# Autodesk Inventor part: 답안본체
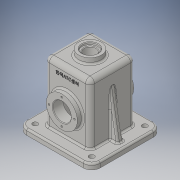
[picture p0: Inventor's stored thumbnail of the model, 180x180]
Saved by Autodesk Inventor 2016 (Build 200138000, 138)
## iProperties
Created: 2022-11
Part Number: 답안본체
Material: 일반
Document SubType Name: Modeling
Designer: CAD-13
Density: 1 g/cm^3
Appearance: 기본값
Author: CAD-13
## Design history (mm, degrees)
sketch "스케치1"
  geometry: L1 (40, -40)-(-40, -40); L2 (-40, -40)-(-40, 40); L3 (-40, 40)-(40, 40); L4 (40, 40)-(40, -40); L5 (40, -40)-(-40, 40); L6 (-40, -40)-(40, 40); 1 further point
  constraints: 12 end point, 2 midpoint, 2 parallel, 1 horizontal, 1 perpendicular
  dimensions: "d0" = 80 distance of L2.end L3.end; "d1" = 80 distance of L1.end L2.end
extrude "돌출1" new body sketch "스케치1" distance "d2" = 117; taper "d3" = 0 deg
feature "쉘1" dims "d4" = 8
node "작업 평면1"
sketch "스케치3"
  geometry: L1 (65, -62)-(-65, -62); L2 (-65, -62)-(-65, 62); L3 (-65, 62)-(65, 62); L4 (65, 62)-(65, -62); L5 (65, -62)-(-65, 62); L6 (-65, -62)-(65, 62); 1 further point
  constraints: 12 end point, 2 midpoint, 2 parallel, 1 horizontal, 1 perpendicular
  dimensions: "d6" = 130 distance of L2.end L3.end; "d7" = 124 distance of L1.end L2.end
extrude "돌출2" join sketch "스케치3" distance "d8" = 10; taper "d9" = 0 deg
sketch "스케치4"
  geometry: L1 (105, -117)-(-25, -117) reference; L2 (0, 0)-(80, 0) reference; C1 r 27.5 at (40, -62); 2 further points
  constraints: 1 centre point, 1 midpoint, 1 vertical alignment
  dimensions: "d10" = 55 diameter of C1; "d11" = 55 distance from line of L1 C1.centre
extrude "돌출3" join sketch "스케치4" distance "d12" = 10; taper "d13" = 0 deg
sketch "스케치5"
  geometry: C1 r 16 at (0, 0); 1 further point
  constraints: 1 centre point
  dimensions: "d14" = 32 diameter of C1
extrude "돌출4" cut sketch "스케치5" stored distance "d15" = 10; taper "d16" = 0 deg
sketch "스케치6"
  geometry: C1 r 20 at (0, 0); 1 further point
  constraints: 1 centre point, 1 coincident
  dimensions: "d17" = 40 diameter of C1
extrude "돌출5" join sketch "스케치6" distance "d18" = 10; taper "d19" = 0 deg
node "작업 평면2"
sketch "스케치7"
  geometry: L1 (40, 10)-(40, 117); L2 (40, 91.279)-(54.332, 10); L3 (-62, 10)-(64.332, 10); L4 (40, 10)-(40, 91.279); L5 (40, 10)-(54.332, 10); 1 further point
  constraints: 10 end point, 2 point on line
  dimensions: "d21" = 10 distance of L2.end L3.end; "d22" = 100 deg angle of L3 L2
extrude "돌출6" join sketch "스케치7" stored distance "d23" = 10; taper "d24" = 0 deg
sketch "스케치8"
  geometry: C1 r 14 at (0, 0); 1 further point
  constraints: 1 centre point, 1 coincident
  dimensions: "d25" = 28 diameter of C1
extrude "돌출7" cut sketch "스케치8" distance "d26" = 4; taper "d27" = 0 deg
sketch "스케치9"
  geometry: C1 r 10.5 at (0, 0); 1 further point
  constraints: 1 centre point, 1 coincident
  dimensions: "d28" = 21 diameter of C1
extrude "돌출8" cut sketch "스케치9" stored distance "d29" = 4; taper "d30" = 0 deg
fillet "모깎기1" dims "d31" = 8
fillet "모깎기2" dims "d32" = 8
fillet "모깎기3" dims "d33" = 15
fillet "모깎기4" dims "d34" = 3
sketch "스케치10"
  geometry: C1 r 4.5 at (-50, 47); C2 r 4.5 at (50, 47); C3 r 4.5 at (50, -47); C4 r 4.5 at (-50, -47); A1 r 15 centre (-50, 47) between (-50, 62) and (-65, 47) reference; A2 r 12 centre (50, 47) between (62, 47) and (50, 59) reference; A3 r 12 centre (50, -47) between (50, -59) and (62, -47) reference; A4 r 15 centre (-50, -47) between (-65, -47) and (-50, -62) reference; 1 further point
  constraints: 4 centre point, 4 coincident
  dimensions: "d35" = 9 diameter of C1; "d36" = 9 diameter of C2; "d37" = 9 diameter of C3; "d38" = 9 diameter of C4
extrude "돌출9" cut sketch "스케치10" stored distance "d39" = 0; taper "d40" = 0 deg
sketch "스케치11" dims "d41" = 45
  geometry: 3 further points
  constraints: 2 vertical alignment, 2 other
hole "구멍1" sketch "스케치11" at (0, 22.5) diameter "d42" = 3.242; stored, may be unused: countersink angle "d46" = 90 deg, drill point angle "d48" = 118 deg; dims "d43" = 8, "d44" = 4, "d45" = 2, "d47" = 10
fillet "모깎기5" dims "d52" = 3
fillet "모깎기6" dims "d53" = 3
chamfer "모따기1" distance "d54" = 1; stored, may be unused: second distance "d55" = 2, angle "d56" = 45 deg
chamfer "모따기2" distance "d57" = 1; stored, may be unused: second distance "d58" = 2, angle "d59" = 45 deg
fillet "모깎기7" dims "d60" = 3
fillet "모깎기8" dims "d61" = 3
sketch "스케치12"
  geometry: L1 (-32, -32)-(32, -32); L2 (32, -32)-(32, 32); L3 (32, 32)-(-32, 32); L4 (-32, 32)-(-32, -32); L5 (-32, -32)-(32, 32); L6 (32, -32)-(-32, 32); 1 further point
  constraints: 12 end point, 2 midpoint, 2 parallel, 1 horizontal, 1 perpendicular
  dimensions: "d62" = 64 distance of L3.end L2.end; "d63" = 64 distance of L2.end L1.end
extrude "돌출10" cut sketch "스케치12" stored distance "d64" = 4; taper "d65" = 0 deg
sketch "스케치13"
  geometry: L1 (82, -10)-(-18, -10) reference; L2 (52, 117)-(12, 117) reference; 3 further points
  constraints: 1 midpoint, 1 vertical alignment, 1 other
  dimensions: "d66" = 25 distance from line of L2 point (32, 92)
feature "엠보싱1" sketch "스케치13" dims "d10" = 55, "d11" = 55, "d67" = 0.5, "d68" = 0
fillet "모깎기9" dims "d69" = 3
fillet "모깎기10" dims "d70" = 3
node "솔리드1"
mirror "대칭1"
mirror "대칭2"
pattern_circular "원형 패턴1" dims angle "d50" = 360 deg
mirror "대칭3"
other parameters: "d5" = 0, "d20" = 0
